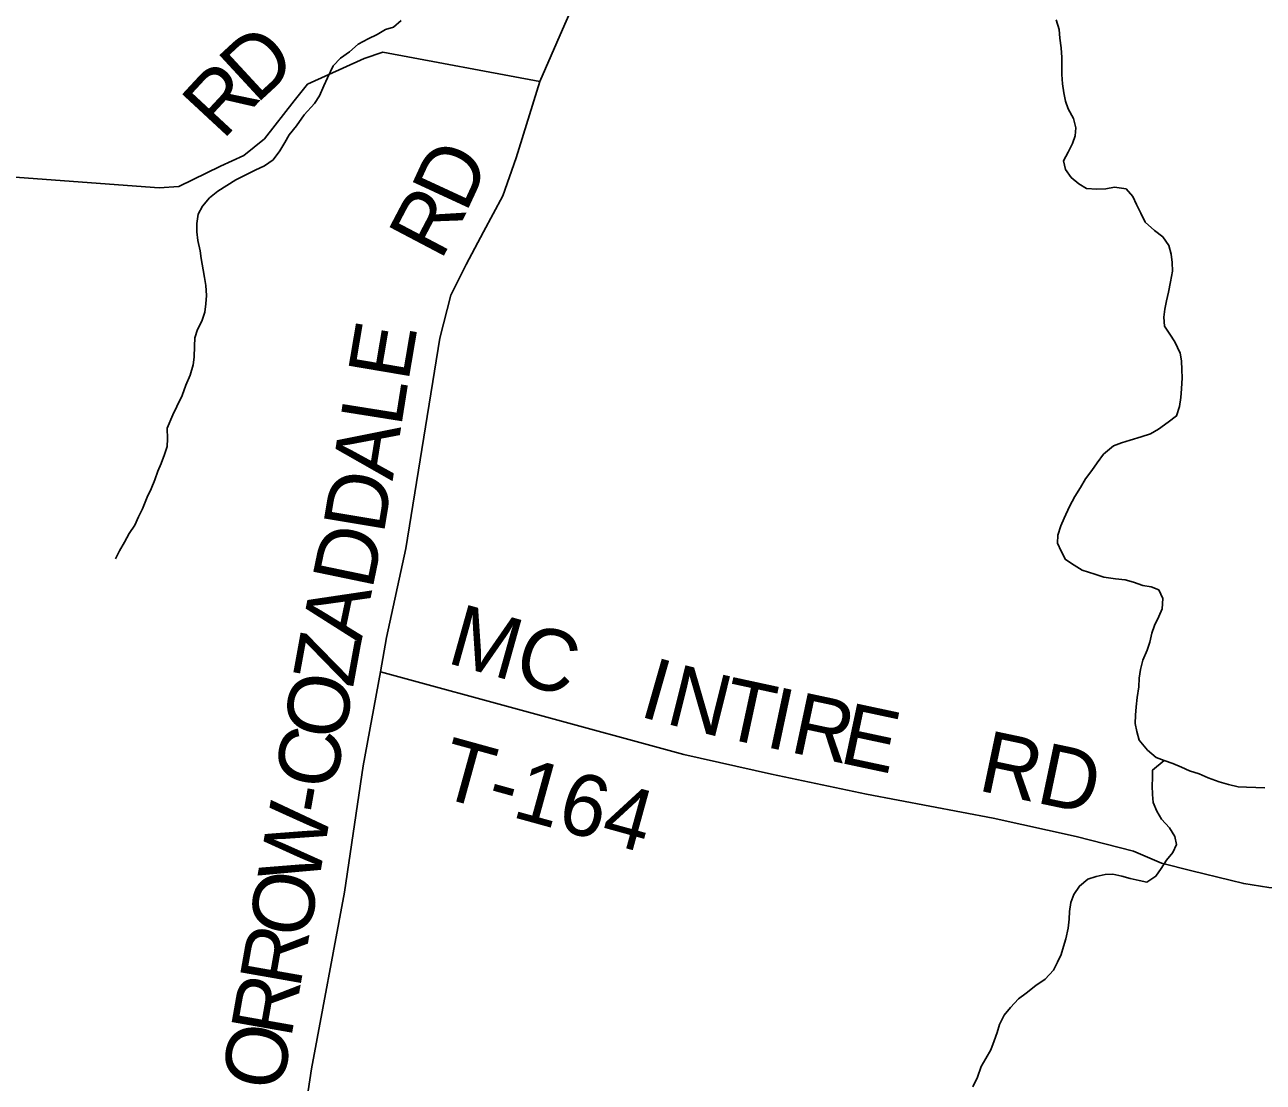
# Model space of a CAD drawing. Extents: x 0 to 34, y -4 to 22.
# Drawn here: x 7.021 to 7.827, y 15.668 to 16.356 of the extents above; entities that cross this region are included whole.
import ezdxf

# ---------------------------------------------------------------- set-up
doc = ezdxf.new("R2010")
doc.units = 0
for name, color, linetype in [('GM_X_County_Road', 7, 'Continuous'), ('GM_X_County_Road_Text', 7, 'Continuous'), ('GM_X_Minor_River', 7, 'Continuous'), ('GM_X_Township_Road', 7, 'Continuous'), ('GM_X_Township_Road_Text', 7, 'Continuous')]:
    doc.layers.add(name, color=color, linetype=linetype)

msp = doc.modelspace()

# ---------------------------------------------------------------- linework, layer by layer
at = {"layer": 'GM_X_County_Road'}
for points in [[(7.57799, 16.6662), (7.58031, 16.65128), (7.581, 16.62689), (7.57651, 16.60435), (7.57181, 16.5962), (7.56294, 16.58462), (7.5524, 16.57397), (7.54436, 16.56311), (7.53538, 16.54558), (7.52954, 16.52783), (7.51993, 16.51175), (7.51054, 16.50257), (7.50177, 16.49338), (7.49092, 16.48419), (7.46544, 16.45643), (7.44415, 16.4366), (7.4145, 16.40987), (7.39655, 16.3986), (7.38695, 16.39108), (7.37879, 16.37141), (7.37069, 16.35312), (7.35605, 16.31926)], [(7.35605, 16.31926), (7.3406, 16.26958), (7.33183, 16.24494), (7.3193, 16.22156), (7.30803, 16.20026), (7.29801, 16.18022), (7.29091, 16.15225), (7.26886, 16.01556), (7.25621, 15.95766), (7.25237, 15.9353), (7.24103, 15.87408), (7.22881, 15.79179), (7.2074, 15.67699), (7.20405, 15.6554)]]:
    msp.add_lwpolyline(points, dxfattribs=at)
at = {"layer": 'GM_X_Minor_River'}
for points in [[(7.07993, 16.00876), (7.08243, 16.01407), (7.08573, 16.01963), (7.08877, 16.02519), (7.09234, 16.03075), (7.09483, 16.03606), (7.09733, 16.04136), (7.1004, 16.0488), (7.10316, 16.05437), (7.1054, 16.06022), (7.10737, 16.0658), (7.10959, 16.07084), (7.11183, 16.07669), (7.11352, 16.08174), (7.1136, 16.08682), (7.11345, 16.09377), (7.11708, 16.10254), (7.11984, 16.10784), (7.12317, 16.11501), (7.12569, 16.12165), (7.12848, 16.12829), (7.13046, 16.13494), (7.13108, 16.14001), (7.1312, 16.14723), (7.13156, 16.15257), (7.13325, 16.15789), (7.13602, 16.16346), (7.13799, 16.16931), (7.13861, 16.17464), (7.13897, 16.17998), (7.13855, 16.18668), (7.13783, 16.19177), (7.13685, 16.19686), (7.13563, 16.2041), (7.13491, 16.20919), (7.13342, 16.2159), (7.13271, 16.22152), (7.1328, 16.22687), (7.13371, 16.233), (7.13647, 16.2383), (7.14111, 16.24358), (7.14653, 16.24803), (7.15221, 16.25169), (7.15815, 16.25533), (7.16382, 16.25819), (7.17083, 16.26155), (7.17676, 16.2644), (7.18245, 16.26832), (7.18682, 16.27413), (7.19013, 16.27969), (7.19289, 16.28472), (7.19753, 16.29053), (7.20273, 16.29767), (7.20927, 16.30505), (7.21257, 16.31008), (7.21535, 16.31645), (7.21785, 16.32175), (7.22145, 16.32945), (7.22635, 16.33445), (7.23204, 16.33864), (7.23774, 16.34363), (7.24422, 16.347), (7.25015, 16.34984), (7.25556, 16.35323), (7.26066, 16.35476), (7.26582, 16.35895)], [(7.69193, 16.35938), (7.69396, 16.3532), (7.6944, 16.34758), (7.6951, 16.34115), (7.69553, 16.335), (7.6957, 16.32911), (7.69561, 16.32377), (7.69604, 16.31788), (7.69701, 16.31198), (7.698, 16.30662), (7.69978, 16.30151), (7.70316, 16.29531), (7.70466, 16.28914), (7.7043, 16.28406), (7.70261, 16.27901), (7.69985, 16.27344), (7.69681, 16.26761), (7.69805, 16.26198), (7.70171, 16.25684), (7.70672, 16.25275), (7.71175, 16.24973), (7.71843, 16.24935), (7.72432, 16.24953), (7.72995, 16.25051), (7.73743, 16.24959), (7.74189, 16.24444), (7.74421, 16.23932), (7.74706, 16.23366), (7.7499, 16.22773), (7.75596, 16.22229), (7.76124, 16.2182), (7.76516, 16.21252), (7.76667, 16.20688), (7.76738, 16.20152), (7.76756, 16.19591), (7.76637, 16.18897), (7.76492, 16.18231), (7.76376, 16.17672), (7.76259, 16.17112), (7.76197, 16.16606), (7.76241, 16.16017), (7.7658, 16.15503), (7.76919, 16.1499), (7.77255, 16.14263), (7.77353, 16.13753), (7.7737, 16.13165), (7.77388, 16.12657), (7.77349, 16.11936), (7.77313, 16.11375), (7.77223, 16.10788), (7.77026, 16.10176), (7.76484, 16.09757), (7.75861, 16.09313), (7.75321, 16.09), (7.74729, 16.08823), (7.74003, 16.08594), (7.73439, 16.08416), (7.72927, 16.08237), (7.72276, 16.07686), (7.71866, 16.07131), (7.7151, 16.06628), (7.71099, 16.06074), (7.70769, 16.05517), (7.70411, 16.04935), (7.70052, 16.04272), (7.69719, 16.03529), (7.69497, 16.03025), (7.69299, 16.02413), (7.69291, 16.01905), (7.69522, 16.01367), (7.69807, 16.00828), (7.70363, 16.00471), (7.70893, 16.00142), (7.71718, 15.99888), (7.72303, 15.99692), (7.7305, 15.99573), (7.73691, 15.99509), (7.74223, 15.99367), (7.74835, 15.99144), (7.75368, 15.99055), (7.75873, 15.9886)], [(7.75873, 15.9886), (7.76131, 15.98294), (7.76093, 15.97626), (7.75871, 15.97122), (7.75594, 15.96538), (7.75425, 15.96033), (7.75281, 15.95447), (7.75112, 15.94942), (7.74833, 15.94278), (7.74689, 15.93666), (7.746, 15.93106), (7.74564, 15.92545), (7.74472, 15.91851), (7.74408, 15.91237), (7.74346, 15.90704), (7.74337, 15.90169), (7.74435, 15.89633), (7.74586, 15.89069), (7.75137, 15.88419), (7.75691, 15.87955), (7.76222, 15.8776), (7.76781, 15.87564), (7.77338, 15.87314), (7.7787, 15.87092), (7.78508, 15.86895), (7.79092, 15.86618), (7.7981, 15.86366), (7.80396, 15.86196), (7.81035, 15.86052), (7.8157, 15.86017), (7.82185, 15.86007), (7.82773, 15.85971)], [(7.63777, 15.66518), (7.64082, 15.67154), (7.64308, 15.67846), (7.64611, 15.68376), (7.64941, 15.68932), (7.65165, 15.69516), (7.65361, 15.70048), (7.65503, 15.7058), (7.65808, 15.7119), (7.66218, 15.71692), (7.66735, 15.72245), (7.67249, 15.72611), (7.67873, 15.73109), (7.68468, 15.73527), (7.69013, 15.74107), (7.69289, 15.74637), (7.69512, 15.75141), (7.69681, 15.75647), (7.69823, 15.76152), (7.69968, 15.76845), (7.70031, 15.77432), (7.70067, 15.7794), (7.70157, 15.78526), (7.70352, 15.79031), (7.70709, 15.79587), (7.71252, 15.80033), (7.7179, 15.80211), (7.7238, 15.80336), (7.72889, 15.80354), (7.73475, 15.80238), (7.74007, 15.80069), (7.74594, 15.79953), (7.751, 15.79838), (7.75669, 15.8023), (7.76025, 15.80732), (7.76381, 15.81261), (7.76791, 15.81762), (7.77014, 15.82294), (7.76915, 15.82803), (7.76577, 15.8337), (7.76051, 15.8394), (7.75739, 15.84452), (7.75508, 15.85018), (7.75463, 15.85553), (7.75446, 15.86115), (7.75454, 15.86622), (7.75463, 15.8713), (7.76222, 15.8776)]]:
    msp.add_lwpolyline(points, dxfattribs=at)
at = {"layer": 'GM_X_Township_Road'}
for points in [[(6.68317, 16.28166), (7.10834, 16.25016), (7.12107, 16.251), (7.14811, 16.26415), (7.16346, 16.27125), (7.17692, 16.2821), (7.19613, 16.30674), (7.20489, 16.31759), (7.24164, 16.3343), (7.25375, 16.33847), (7.35605, 16.31926)], [(7.25237, 15.9353), (7.44971, 15.88142), (7.50676, 15.86874), (7.56848, 15.85574), (7.65089, 15.84005), (7.70493, 15.82805), (7.74229, 15.81854), (7.76048, 15.8107), (7.78016, 15.80586), (7.80509, 15.79972)], [(7.80509, 15.79972), (7.81402, 15.79752), (7.83037, 15.79501), (7.8611, 15.79339), (7.87484, 15.79197)]]:
    msp.add_lwpolyline(points, dxfattribs=at)

# ---------------------------------------------------------------- texts
at = {"layer": 'GM_X_County_Road_Text'}
for s, rotation, p in [('D', 65.1761, (7.3078, 16.23313)), ('R', 62.24618, (7.29153, 16.20209)), ('E', 80.38055, (7.27035, 16.12337)), ('L', 80.96744, (7.26567, 16.09392)), ('A', 80.97422, (7.26014, 16.05916)), ('D', 80.54647, (7.25431, 16.02412)), ('D', 78.27753, (7.24684, 15.98795)), ('A', 78.19426, (7.23963, 15.95343)), ('Z', 79.6802, (7.23432, 15.92427)), ('O', 79.99686, (7.22822, 15.88966)), ('C', 79.99779, (7.22251, 15.85731)), ('-', 79.99608, (7.21966, 15.84113)), ('W', 79.99778, (7.21161, 15.79549)), ('O', 79.9975, (7.20549, 15.76082)), ('R', 80.00005, (7.19979, 15.72847)), ('R', 79.99676, (7.19408, 15.69611)), ('O', 79.9975, (7.18797, 15.66144))]:
    msp.add_text(s, height=0.04, rotation=rotation, dxfattribs=at).set_placement(p)
at = {"layer": 'GM_X_Township_Road_Text'}
for s, rotation, p in [('D', 42.74295, (7.17139, 16.30413)), ('R', 47.1642, (7.14963, 16.28062)), ('MC', 344.35782, (7.29449, 15.94131)), ('I', 344.04174, (7.41958, 15.90665)), ('N', 346.01186, (7.4368, 15.90175)), ('T', 347.81426, (7.47227, 15.89294)), ('I', 347.97284, (7.50163, 15.8866)), ('R', 347.97285, (7.5177, 15.88317)), ('E', 347.97229, (7.54983, 15.87633)), ('T-164', 344.59628, (7.28823, 15.85453)), ('RD', 348.11076, (7.64015, 15.85825))]:
    msp.add_text(s, height=0.04, rotation=rotation, dxfattribs=at).set_placement(p)

doc.saveas('drawing.dxf')
